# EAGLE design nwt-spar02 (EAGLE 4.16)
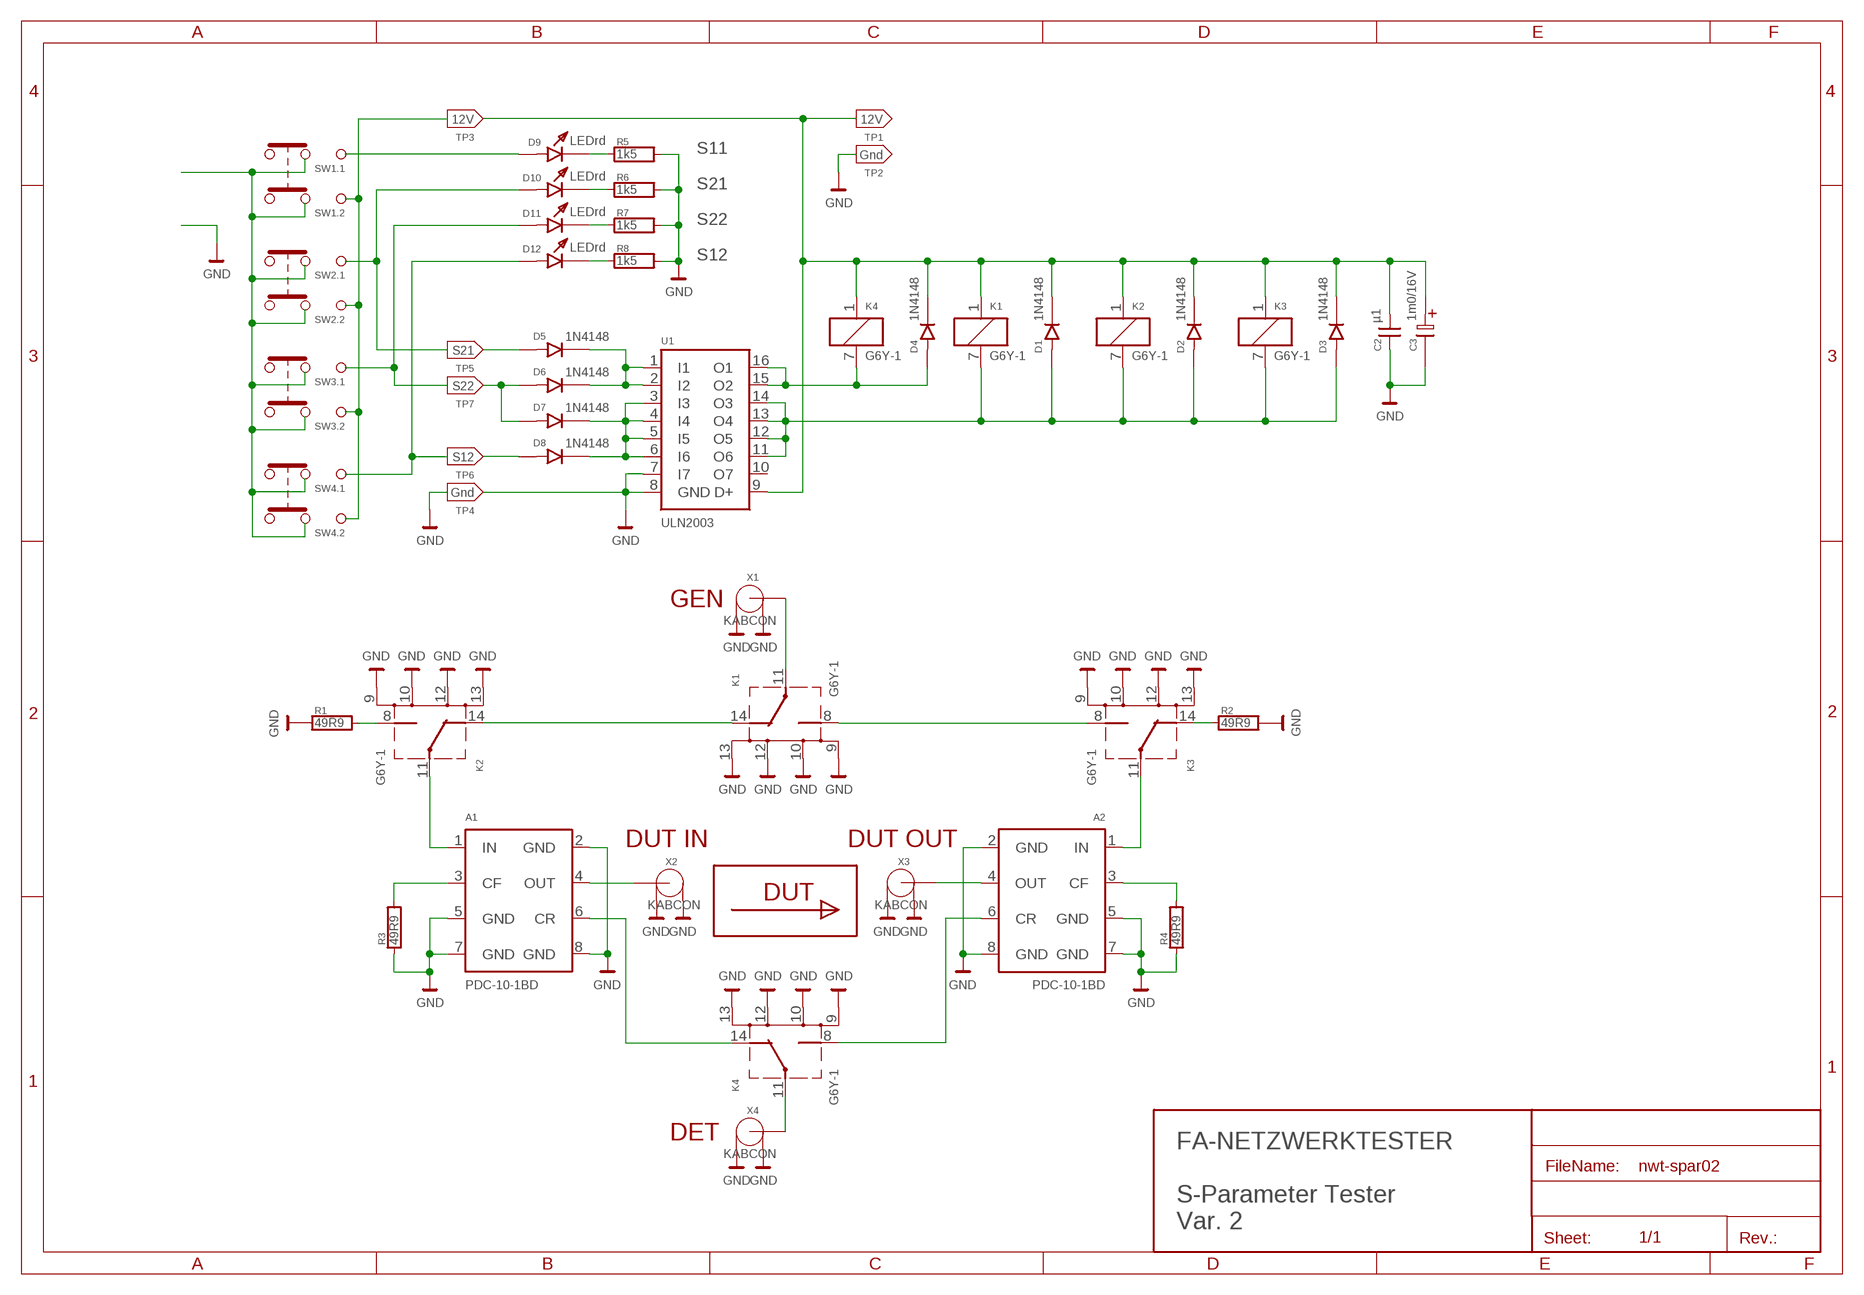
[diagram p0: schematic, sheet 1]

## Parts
A1  PDC-10-1BD  PDC-10DB  [DBM-1]
A2  PDC-10-1BD  PDC-10DB  [DBM-1]
C2  µ1  CNP-5  [C-5SN]
C3  1m0/16V  ELC-5  [ES-5]
D1  1N4148  DIODE-10  [D-10]
D2  1N4148  DIODE-10  [D-10]
D3  1N4148  DIODE-10  [D-10]
D4  1N4148  DIODE-10  [D-10]
D5  1N4148  DIODE-10  [D-10]
D6  1N4148  DIODE-10  [D-10]
D7  1N4148  DIODE-10  [D-10]
D8  1N4148  DIODE-10  [D-10]
D9  LEDrd  LED-01  [LED3-F]
D10  LEDrd  LED-01  [LED3-F]
D11  LEDrd  LED-01  [LED3-F]
D12  LEDrd  LED-01  [LED3-F]
K1  G6Y-1  G5Y-3  [G5Y-2]
K2  G6Y-1  G5Y-3  [G5Y-2]
K3  G6Y-1  G5Y-3  [G5Y-2]
K4  G6Y-1  G5Y-3  [G5Y-2]
R1  49R9  1206R  [1206R]
R2  49R9  1206R  [1206R]
R3  49R9  1206R  [1206R]
R4  49R9  1206R  [1206R]
R5  1k5  RESEU-10  [R-10]
R6  1k5  RESEU-10  [R-10]
R7  1k5  RESEU-10  [R-10]
R8  1k5  RESEU-10  [R-10]
TP1  12V  TP2OUT  [TP1]
TP2  Gnd  TP2OUT  [TP1]
TP3  12V  TP2IN  [TP1]
TP4  Gnd  TP2IN  [TP1]
TP5  S21  TP2IN  [TP1]
TP6  S12  TP2IN  [TP1]
TP7  S22  TP2IN  [TP1]
U1  ULN2003  ULN2003A  [DIL16S]
X1  KABCON  KABCON2  [KOAX-CABCON2]
X2  KABCON  KABCON2  [KOAX-CABCON2]
X3  KABCON  KABCON2  [KOAX-CABCON2]
X4  KABCON  KABCON2  [KOAX-CABCON2]

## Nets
+12V: C2.1 C3.1 D1.2(K) D2.2(K) D3.2(K) D4.2(K) K1.1 K2.1 K3.1 K4.1 TP1.1 TP3.1 U1.9(D+)
GND: A1.2(GND) A1.5(GND) A1.7(GND) A1.8(GND) A2.2(GND) A2.5(GND) A2.7(GND) A2.8(GND) C2.2 C3.2 K1.9(ES) K1.10(ES) K1.12(ES) K1.13(ES) K2.9(ES) K2.10(ES) K2.12(ES) K2.13(ES) K3.9(ES) K3.10(ES) K3.12(ES) K3.13(ES) K4.9(ES) K4.10(ES) K4.12(ES) K4.13(ES) R1.1 R2.2 R3.1 R4.1 R5.2 R6.2 R7.2 R8.2 TP2.1 TP4.1 U1.7(I7) U1.8(GND) X1.GND X1.GND@1(GND) X2.GND X2.GND@1(GND) X3.GND X3.GND@1(GND) X4.GND X4.GND@1(GND)
N$1: D1.1(A) D2.1(A) D3.1(A) K1.7 K2.7 K3.7 U1.11(O6) U1.12(O5) U1.13(O4) U1.14(O3)
N$2: A1.4(OUT) X2.1
N$3: A1.3(CF) R3.2
N$4: K3.14(O) R2.1
N$5: K2.8(S) R1.2
N$6: A1.1(IN) K2.11(P)
N$7: A2.4(OUT) X3.1
N$8: A1.6(CR) K4.14(O)
N$10: A2.3(CF) R4.2
N$11: A2.6(CR) K4.8(S)
N$12: A2.1(IN) K3.11(P)
N$13: D8.1(A) TP6.1
N$15: K4.11(P) X4.1
N$18: D4.1(A) K4.7 U1.15(O2) U1.16(O1)
N$22: K1.11(P) X1.1
N$23: K1.14(O) K2.14(O)
N$25: D5.2(K) D6.2(K) U1.1(I1) U1.2(I2)
N$26: D7.2(K) D8.2(K) U1.3(I3) U1.4(I4) U1.5(I5) U1.6(I6)
N$29: K1.8(S) K3.8(S)
N$34: D5.1(A) TP5.1
N$39: D6.1(A) D7.1(A) TP7.1
N$44: D9.A
N$46: D11.A
N$47: D12.A
N$48: D10.A
S$3: D9.K R5.1
S$4: D10.K R6.1
S$6: D11.K R7.1
S$9: D12.K R8.1
Unconnected: U1.10(O7)

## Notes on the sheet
- S11
- SW1.1
- S21
- SW1.2
- S22
- S12
- SW2.1
- SW2.2
- SW3.1
- SW3.2
- SW4.1
- SW4.2
- GEN
- DUT IN | DUT OUT
- DUT
- DET
- FA-NETZWERKTESTER
- S-Parameter Tester
- Var. 2

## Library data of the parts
A1 A2 = 1oldSPECIAL:PDC-10DB
C2 = oldDISCRE-N:CNP-5
C3 = oldDISCRE-N:ELC-5
D1-D8 = oldDISCRE-N:DIODE-10
D9-D12 = oldDISCRE-N:LED-01
K1-K4 = relay:G5Y-3
R1-R4 = oldSMD-DIS:1206R
R5-R8 = oldDISCRE-N:RESEU-10
TP1 TP2 = supply2:TP2OUT
TP3-TP7 = supply2:TP2IN
U1 = uln-udn:ULN2003A: DRIVER ARRAY
X1-X4 = 1oldSPECIAL:KABCON2

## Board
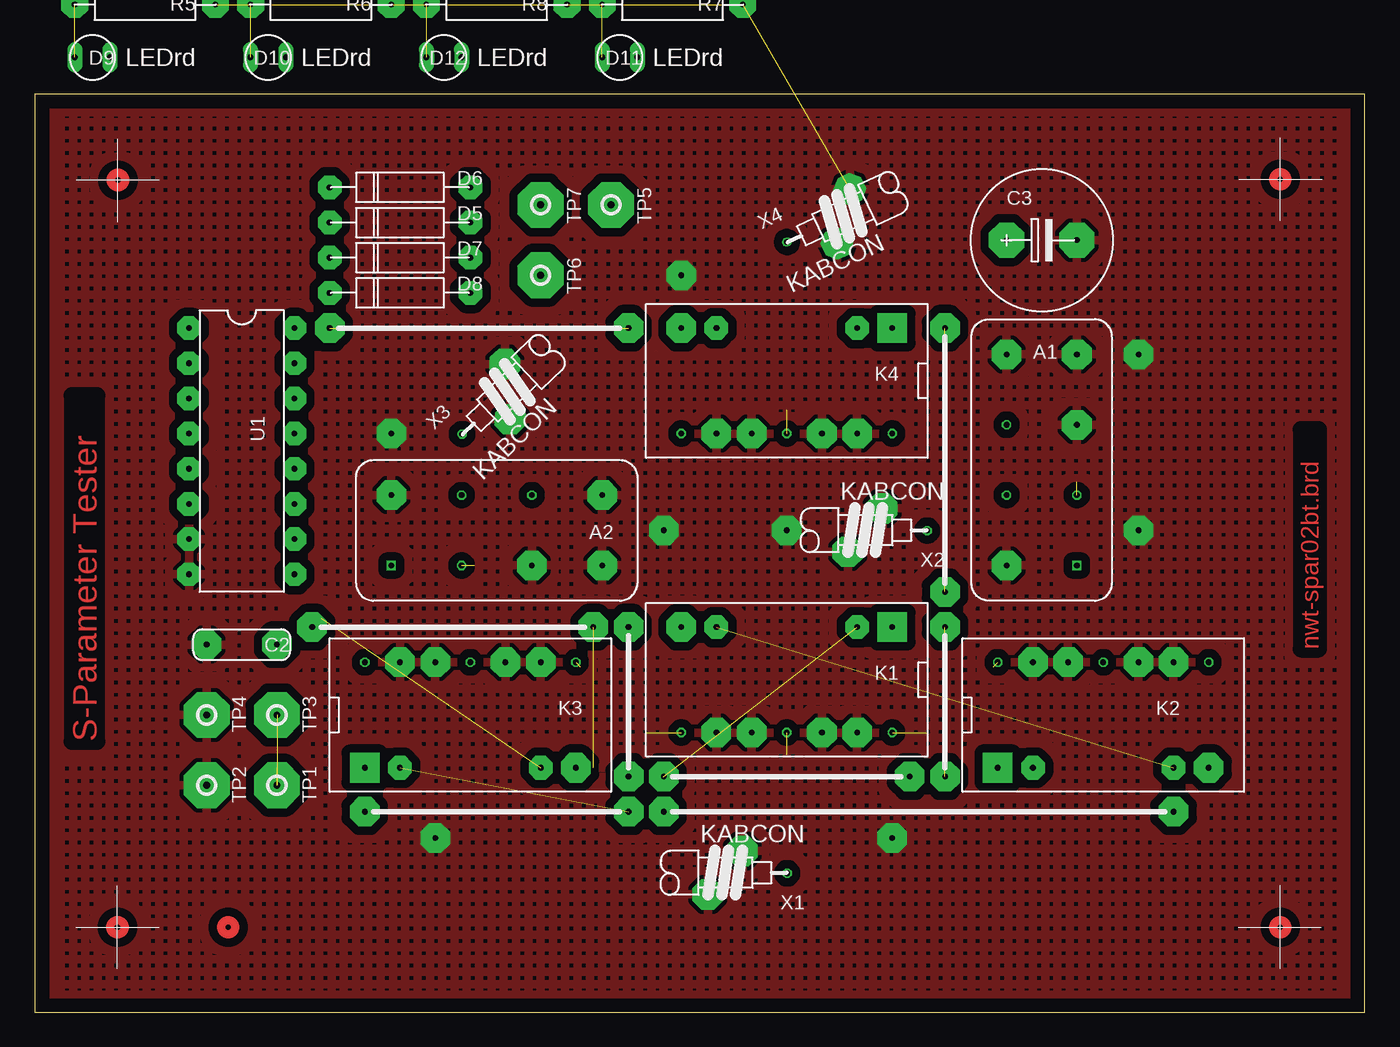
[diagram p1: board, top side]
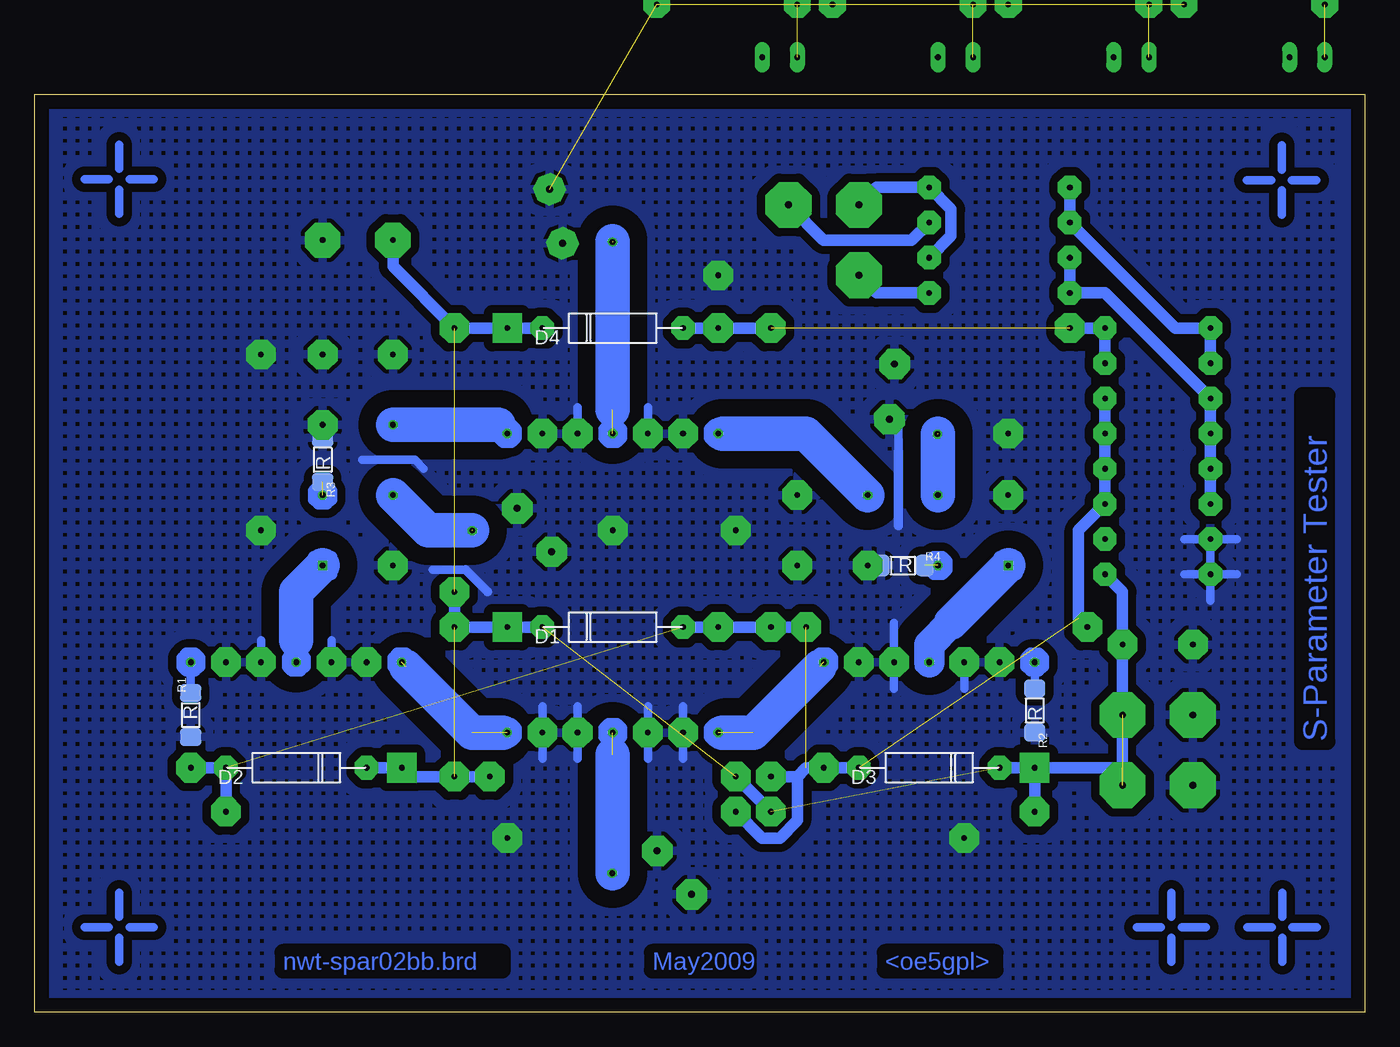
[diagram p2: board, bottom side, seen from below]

Size 96.09 x 66.31 mm. Coordinates in mm from the lower left corner, seen from the top.
Outline: 0,0 96.09,0 96.09,66.31 0,66.31 0,0
Copper layers (1*16): Top 0.035mm / dielectric 1.5mm / Bottom 0.035mm
Design rules "default": minimum track width 10mil, minimum drill 24mil, track to track 8mil, track to pad 8mil, pad to pad 8mil, via to via 8mil, smd to smd 8mil, copper to edge 40mil, drill to drill 8mil, minimum pad ring 5mil, minimum via ring 8mil, stop-mask expansion 4mil, vias tented up to drill 0mil, thermal gap 12mil
bRestrict: 16 lines

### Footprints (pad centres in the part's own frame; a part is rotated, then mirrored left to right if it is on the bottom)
DBM-1 = drill 0.406 pad 0.61 square: 1 -7.62,-2.54 | drill 0.406 pad 2.134 octagon: 2 -7.62,2.54; 5 2.54,-2.54; 7 7.62,-2.54; 8 7.62,2.54 | drill 0.406 pad 0.61 octagon: 3 -2.54,-2.54; 4 -2.54,2.54; 6 2.54,2.54
C-5SN = drill 0.406 pad 2.134 octagon: 1 2.54,0; 2 -2.54,0
ES-5 = drill 0.406 pad 2.54 octagon: 1 -2.54,0; 2 2.54,0
D-10 = drill 0.406 pad 1.7 octagon: 1 -5.08,0; 2 5.08,0
LED3-F = drill 0.406 pad 1.092 long: A 0,1.27; K 0,-1.27
G5Y-2 = drill 0.406 pad 2.134 square: 1 -7.62,-3.81 | drill 0.406 pad 2.134 octagon: 7 7.62,-3.81; 9 5.08,3.81; 10 2.54,3.81; 12 -2.54,3.81; 13 -5.08,3.81 | drill 0.406 pad 0.61 octagon: 8 7.62,3.81; 11 0,3.81; 14 -7.62,3.81
1206R = smd 1.27 x 1.524: 1 -1.587,0; 2 1.587,0
R-10 = drill 0.406 pad 1.93 octagon: 1 -5.08,0; 2 5.08,0
TP1 = drill 0.5 pad 3.302 octagon: 1 0,0
DIL16S = drill 0.406 pad 1.676 octagon: 1 -8.89,-3.81; 2 -6.35,-3.81; 3 -3.81,-3.81; 4 -1.27,-3.81; 5 1.27,-3.81; 6 3.81,-3.81; 7 6.35,-3.81; 8 8.89,-3.81; 9 8.89,3.81; 10 6.35,3.81; 11 3.81,3.81; 12 1.27,3.81; 13 -1.27,3.81; 14 -3.81,3.81; 15 -6.35,3.81; 16 -8.89,3.81
KOAX-CABCON2 = drill 0.406 pad 0.61 octagon: 1 -7.255,0 | drill 0.5 pad 2.2 octagon: GND -1.522,1.522; GND@1 -4.015,-1.613

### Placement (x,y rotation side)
A1  72.75,39.89 90 top
A2  33.38,34.81 0 top
C2  14.96,26.55 0 top
C3  72.75,55.76 0 top
D1  54.34,27.82 180 bottom
D2  77.2,17.66 0 bottom
D3  31.48,17.66 0 bottom
D4  54.34,49.41 180 bottom
D5  26.39,57.03 180 top
D6  26.39,59.57 180 top
D7  26.39,54.49 180 top
D8  26.39,51.95 180 top
D9  4.17,68.96 270 top
D10  16.87,68.96 270 top
D11  42.27,68.96 270 top
D12  29.57,68.96 270 top
K1  54.34,24.01 180 top
K2  77.2,21.47 0 top
K3  31.48,21.47 0 top
K4  54.34,45.6 180 top
R1  84.81,21.47 90 bottom
R2  23.86,21.79 270 bottom
R3  75.29,39.89 270 bottom
R4  33.38,32.27 0 bottom
R5  not placed on the board
R6  not placed on the board
R7  not placed on the board
R8  not placed on the board
TP1  17.51,16.39 0 top
TP2  12.42,16.39 0 top
TP3  17.51,21.47 0 top
TP4  12.42,21.47 270 top
TP5  41.63,58.3 180 top
TP6  36.55,53.22 180 top
TP7  36.55,58.3 180 top
U1  14.96,40.52 270 top
X1  47.11,10.04 180 top
X2  57.22,34.78 180 top
X3  36.13,46.76 43.7 top
X4  60.92,58.7 25.1 top

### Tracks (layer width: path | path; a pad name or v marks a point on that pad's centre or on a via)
+12V  (via drill 0.41 pad 2.13)  (6 unrouted)
  Bottom 0.813: v42.9,14.49 v45.45,17.03 | D4.2 K4.1 v65.77,49.41 70.21,53.86 C3.1 | v63.22,17.03 v65.77,17.03 68.94,17.03 K2.1 D2.2 | v65.77,30.36 v65.77,27.82 K1.1 D1.2 | U1.9 17.51,30.36 C2.1 TP3.1 17.51,17.66 K3.1 | K3.1 D3.2 | K3.1 v23.86,14.49
GND  (via drill 0.41 pad 2.13)  (4 unrouted)
  Bottom 0.61: U1.8 13.06,31.63 | U1.8 11.15,29.73 | 9.25,31.63 U1.8 | 49.25,22.11 K1.9 49.25,18.3 | 51.79,22.11 K1.10 51.79,18.3 | 56.88,22.11 K1.12 56.88,18.3 | 59.41,22.11 K1.13 59.41,18.3 | U1.7 13.06,34.17 | U1.7 9.25,34.17 | U1.8 U1.7 | 28.94,23.38 K3.12 | 34.02,23.38 K3.10 34.02,28.14 | K2.12 74.66,26.87 | K2.10 79.73,26.87 | 72.43,39.89 68.62,39.89 67.99,39.25 | K4.12 56.88,43.7 | K4.10 51.79,43.7 | 64.97,31.95 67.35,31.95 | 33.7,40.52 33.7,42.11 34.02,42.43
  Bottom 0.686: 33.7,35.12 33.7,40.52 | 63.38,30.36 64.97,31.95
  other vias: 79.73,47.51 79.73,34.81 45.45,34.81 25.76,41.79 54.34,34.81 46.71,53.22 61.95,12.58 28.94,12.58
  pour Bottom (isolate 0.61, hatched): 0.99,65.15 95.11,65.15 95.11,1.15 0.99,1.15
  pour Top (isolate 0.61, hatched): 0.99,65.15 95.11,65.15 95.11,1.15 0.99,1.15
N$1  (via drill 0.41 pad 2.13)  (3 unrouted)
  Bottom 0.813: v45.45,14.49 43.54,12.58 42.27,12.58 41,13.85 41,17.03 | 41,17.03 40.36,17.66 K3.7 D3.1 | 41,17.03 v42.9,17.03 | v40.36,27.82 v42.9,27.82 K1.7 D1.1 | v20.05,27.82 20.68,28.46 20.68,34.81 U1.11 U1.12 U1.13 U1.14 | v82.28,14.49 D2.1 K2.7
N$2  (1 unrouted)
  Bottom 2.5: 64.5,34.81 67.67,34.81 A1.4
N$3  (1 unrouted)
N$4
  Bottom 0.61: R2.1 K3.14
N$5
  Bottom 0.61: R1.2 K2.8
N$6
  Bottom 1.778: K2.11 77.2,26.87
  Bottom 2.5: 77.2,26.87 77.2,30.36 A1.1
N$7  (1 unrouted)
  Bottom 2.5: A2.4 30.84,41.79
N$8
  Bottom 1.778: K4.14 62.59,42.43
  Bottom 2.5: 62.59,42.43 A1.6
N$10  (1 unrouted)
N$11
  Bottom 1.778: 46.4,41.79 K4.8
  Bottom 2.5: 46.4,41.79 40.36,41.79 A2.6
N$12
  Bottom 2.184: 29.89,28.14 31.48,26.55 K3.11
  Bottom 2.5: A2.1 29.89,28.14
N$13
  Bottom 0.813: D8.1 35.28,51.95 TP6.1
N$14
  Bottom 0.61: 6.02,60.85 6.02,62.6
N$15  (2 unrouted)
  Bottom 2.5: 54.33,43.53 54.33,55.69
N$16
  Bottom 0.61: 8.52,60.1 6.77,60.1
N$17
  Bottom 0.61: 3.48,6.15 5.23,6.15
N$18  (via drill 0.41 pad 2.13)  (1 unrouted)
  Bottom 0.813: D4.1 K4.7 v42.9,49.41 | U1.15 U1.16 v21.32,49.41
N$19
  Bottom 0.61: 5.98,8.65 5.98,6.9
N$20
  Bottom 0.61: 8.48,6.15 6.73,6.15
N$21
  Bottom 0.61: 3.52,60.1 5.27,60.1
N$22  (2 unrouted)
  Bottom 2.5: 54.34,10.04 54.34,18.61
N$23  (2 unrouted)
  Bottom 2.5: 64.5,20.2 69.26,24.96
N$24
  Bottom 0.61: 6.02,59.35 6.02,57.6
N$25
  Bottom 0.813: U1.2 U1.1 13.69,49.41 D5.2 D6.2
N$26
  Bottom 0.813: U1.6 U1.5 U1.4 U1.3 18.78,51.95 D8.2 D7.2
N$27
  Bottom 0.61: 5.98,3.65 5.98,5.4
N$28
  Bottom 0.61: 89.23,6.15 87.48,6.15
N$29  (2 unrouted)
  Bottom 2.5: 44.17,20.2 39.41,24.96
N$30
  Bottom 0.61: 89.98,8.65 89.98,6.9
N$31
  Bottom 0.61: 90.73,6.15 92.48,6.15
N$32
  Bottom 0.61: 89.98,3.65 89.98,5.4
N$33
  Bottom 0.61: 89.23,60.15 87.48,60.15
N$34
  Bottom 0.813: D5.1 32.74,55.76 39.09,55.76 TP5.1
N$35
  Bottom 0.61: 89.98,60.9 89.98,62.65
N$36
  Bottom 0.61: 90.73,60.15 92.48,60.15
N$37
  Bottom 0.61: 89.98,57.65 89.98,59.4
N$38
  Bottom 0.61: 13.23,6.15 11.48,6.15
N$39
  Bottom 0.813: D7.1 29.89,56.08 29.89,57.99 D6.1 35.28,59.57 TP7.1
N$40
  Bottom 0.61: 13.98,6.9 13.98,8.65
N$42
  Bottom 0.61: 14.73,6.15 16.48,6.15
N$43
  Bottom 0.61: 13.98,3.65 13.98,5.4
S$1
  Bottom 2.5: 64.34,20.18 62.26,20.18
S$2
  Bottom 2.5: 44.34,20.18 46.43,20.18
S$3  (1 unrouted)
S$4  (1 unrouted)
S$6  (1 unrouted)
S$9  (1 unrouted)
(copper drawn outside any net)
  shapes: Top circle x5

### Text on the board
Top: nwt-spar02bt.brd | S-Parameter Tester
Bottom: S-Parameter Tester | <oe5gpl> | May2009 | nwt-spar02bb.brd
